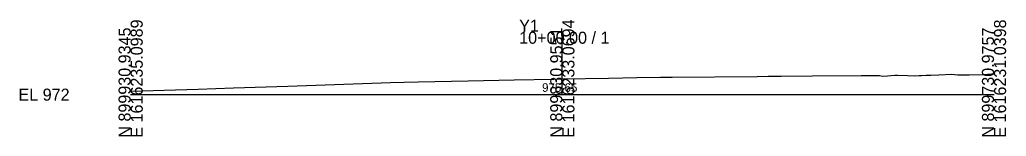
# Model space of a CAD drawing. Extents: x -26 to 203, y -10 to 2022.
# Drawn here: x -25.7 to 202.8, y -9.7 to 17.4 of the extents above; entities that cross this region are included whole.
import ezdxf

# ---------------------------------------------------------------- set-up
doc = ezdxf.new("R2010")
doc.units = 0
for name, color, linetype in [('Exist Cross Section Cell', 7, 'Continuous'), ('Exist XS Center Line Elevation Label', 7, 'Continuous'), ('Exist XS Ground Line', 7, 'Continuous')]:
    doc.layers.add(name, color=color, linetype=linetype)

msp = doc.modelspace()

# ---------------------------------------------------------------- linework, layer by layer
at = {"layer": 'Exist Cross Section Cell'}
for p, q in [((100, 0), (100, 14.64)), ((0, 0), (100, 0)), ((100, 0), (200, 0))]:
    msp.add_line(p, q, dxfattribs=at)
at = {"layer": 'Exist XS Ground Line'}
for p, q in [((185.38, 4.54), (187.22, 4.61)), ((187.22, 4.61), (190.23, 4.73)), ((190.23, 4.73), (190.85, 4.68)), ((190.85, 4.68), (191.63, 4.62)), ((191.63, 4.62), (193.43, 4.64)), ((193.43, 4.64), (194.23, 4.63)), ((194.23, 4.63), (197.46, 4.67)), ((197.46, 4.67), (199.4, 4.83)), ((199.4, 4.83), (200, 4.88)), ((36.43, 2.01), (60.2, 2.8)), ((60.2, 2.8), (63.33, 2.87)), ((63.33, 2.87), (66.62, 2.95)), ((66.62, 2.95), (78.21, 3.21)), ((78.21, 3.21), (88.83, 3.43)), ((88.83, 3.43), (98.05, 3.61)), ((98.05, 3.61), (100, 3.65)), ((100, 3.65), (110.72, 3.87)), ((110.72, 3.87), (117.23, 3.99)), ((117.23, 3.99), (122.73, 4.07)), ((122.73, 4.07), (123.71, 4.07)), ((123.71, 4.07), (124.49, 4.08)), ((124.49, 4.08), (125.48, 4.09)), ((125.48, 4.09), (145.17, 4.24)), ((145.17, 4.24), (147.69, 4.27)), ((147.69, 4.27), (150.7, 4.3)), ((150.7, 4.3), (157.97, 4.37)), ((157.97, 4.37), (169.21, 4.43)), ((169.21, 4.43), (171.27, 4.44)), ((171.27, 4.44), (171.87, 4.44)), ((171.87, 4.44), (173.48, 4.45)), ((173.48, 4.45), (174.13, 4.29)), ((174.13, 4.29), (175.35, 4.4)), ((175.35, 4.4), (176.09, 4.45)), ((176.09, 4.45), (177.04, 4.52)), ((177.04, 4.52), (177.63, 4.54)), ((177.63, 4.54), (179.99, 4.42)), ((179.99, 4.42), (181.58, 4.37)), ((181.58, 4.37), (182.65, 4.43)), ((182.65, 4.43), (183.23, 4.45)), ((183.23, 4.45), (184.27, 4.5)), ((184.27, 4.5), (184.64, 4.51)), ((184.64, 4.51), (185.38, 4.54)), ((0, 0.81), (15.64, 1.3)), ((15.64, 1.3), (23.8, 1.57)), ((23.8, 1.57), (36.43, 2.01))]:
    msp.add_line(p, q, dxfattribs=at)

# ---------------------------------------------------------------- texts
at = {"layer": 'Exist Cross Section Cell'}
for s, p in [('E 1616235.0989', (2.8, -10)), ('E 1616233.0694', (102.8, -10)), ('E 1616231.0398', (202.8, -10)), ('N 899930.9345', (0, -10)), ('N 899830.9551', (100, -10)), ('N 899730.9757', (200, -10))]:
    msp.add_text(s, height=2.8, rotation=90, dxfattribs=at).set_placement(p)
for s, p in [('Y1', (90, 14.64)), ('10+00.00 / 1', (90, 11.84)), ('EL 972', (-26, -1.4))]:
    msp.add_text(s, height=2.8, dxfattribs=at).set_placement(p)
at = {"layer": 'Exist XS Center Line Elevation Label'}
msp.add_text('975.65', height=2, dxfattribs=at).set_placement((95.31, 0.65))

doc.saveas('drawing.dxf')
